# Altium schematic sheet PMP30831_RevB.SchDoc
size 431 x 279 mm; Date: Not shown in title block; ApprovedBy: Not shown in title block; CheckedBy: Not shown in title block; Author: Not shown in title block; CompanyName: Not shown in title block; Engineer: Not shown in title block; Organization: Not shown in title block; Address1: Not shown in title block; Address2: Not shown in title block; Address3: Not shown in title block; Address4: Not shown in title block; DocumentNumber: 2; Revision: Use project parameter SCH_Rev; SheetNumber: 2; SheetTotal: 3; PageSetup: Record=PageOptions¦CenterHorizontal=True¦CenterVertical=True¦PrintScale=1.00¦XCorrection=1.00¦YCorrection=1.00¦PrintKind=0¦BorderSize=5000000¦LeftOffset=0¦BottomOffset=0¦Orientation=2¦PaperLength=1000¦PaperWidth=1000¦Scale=100¦PaperSource=15¦PrintQuality=600¦MediaType=1¦DitherType=10¦PaperKind=Letter¦PrintScaleMode=1
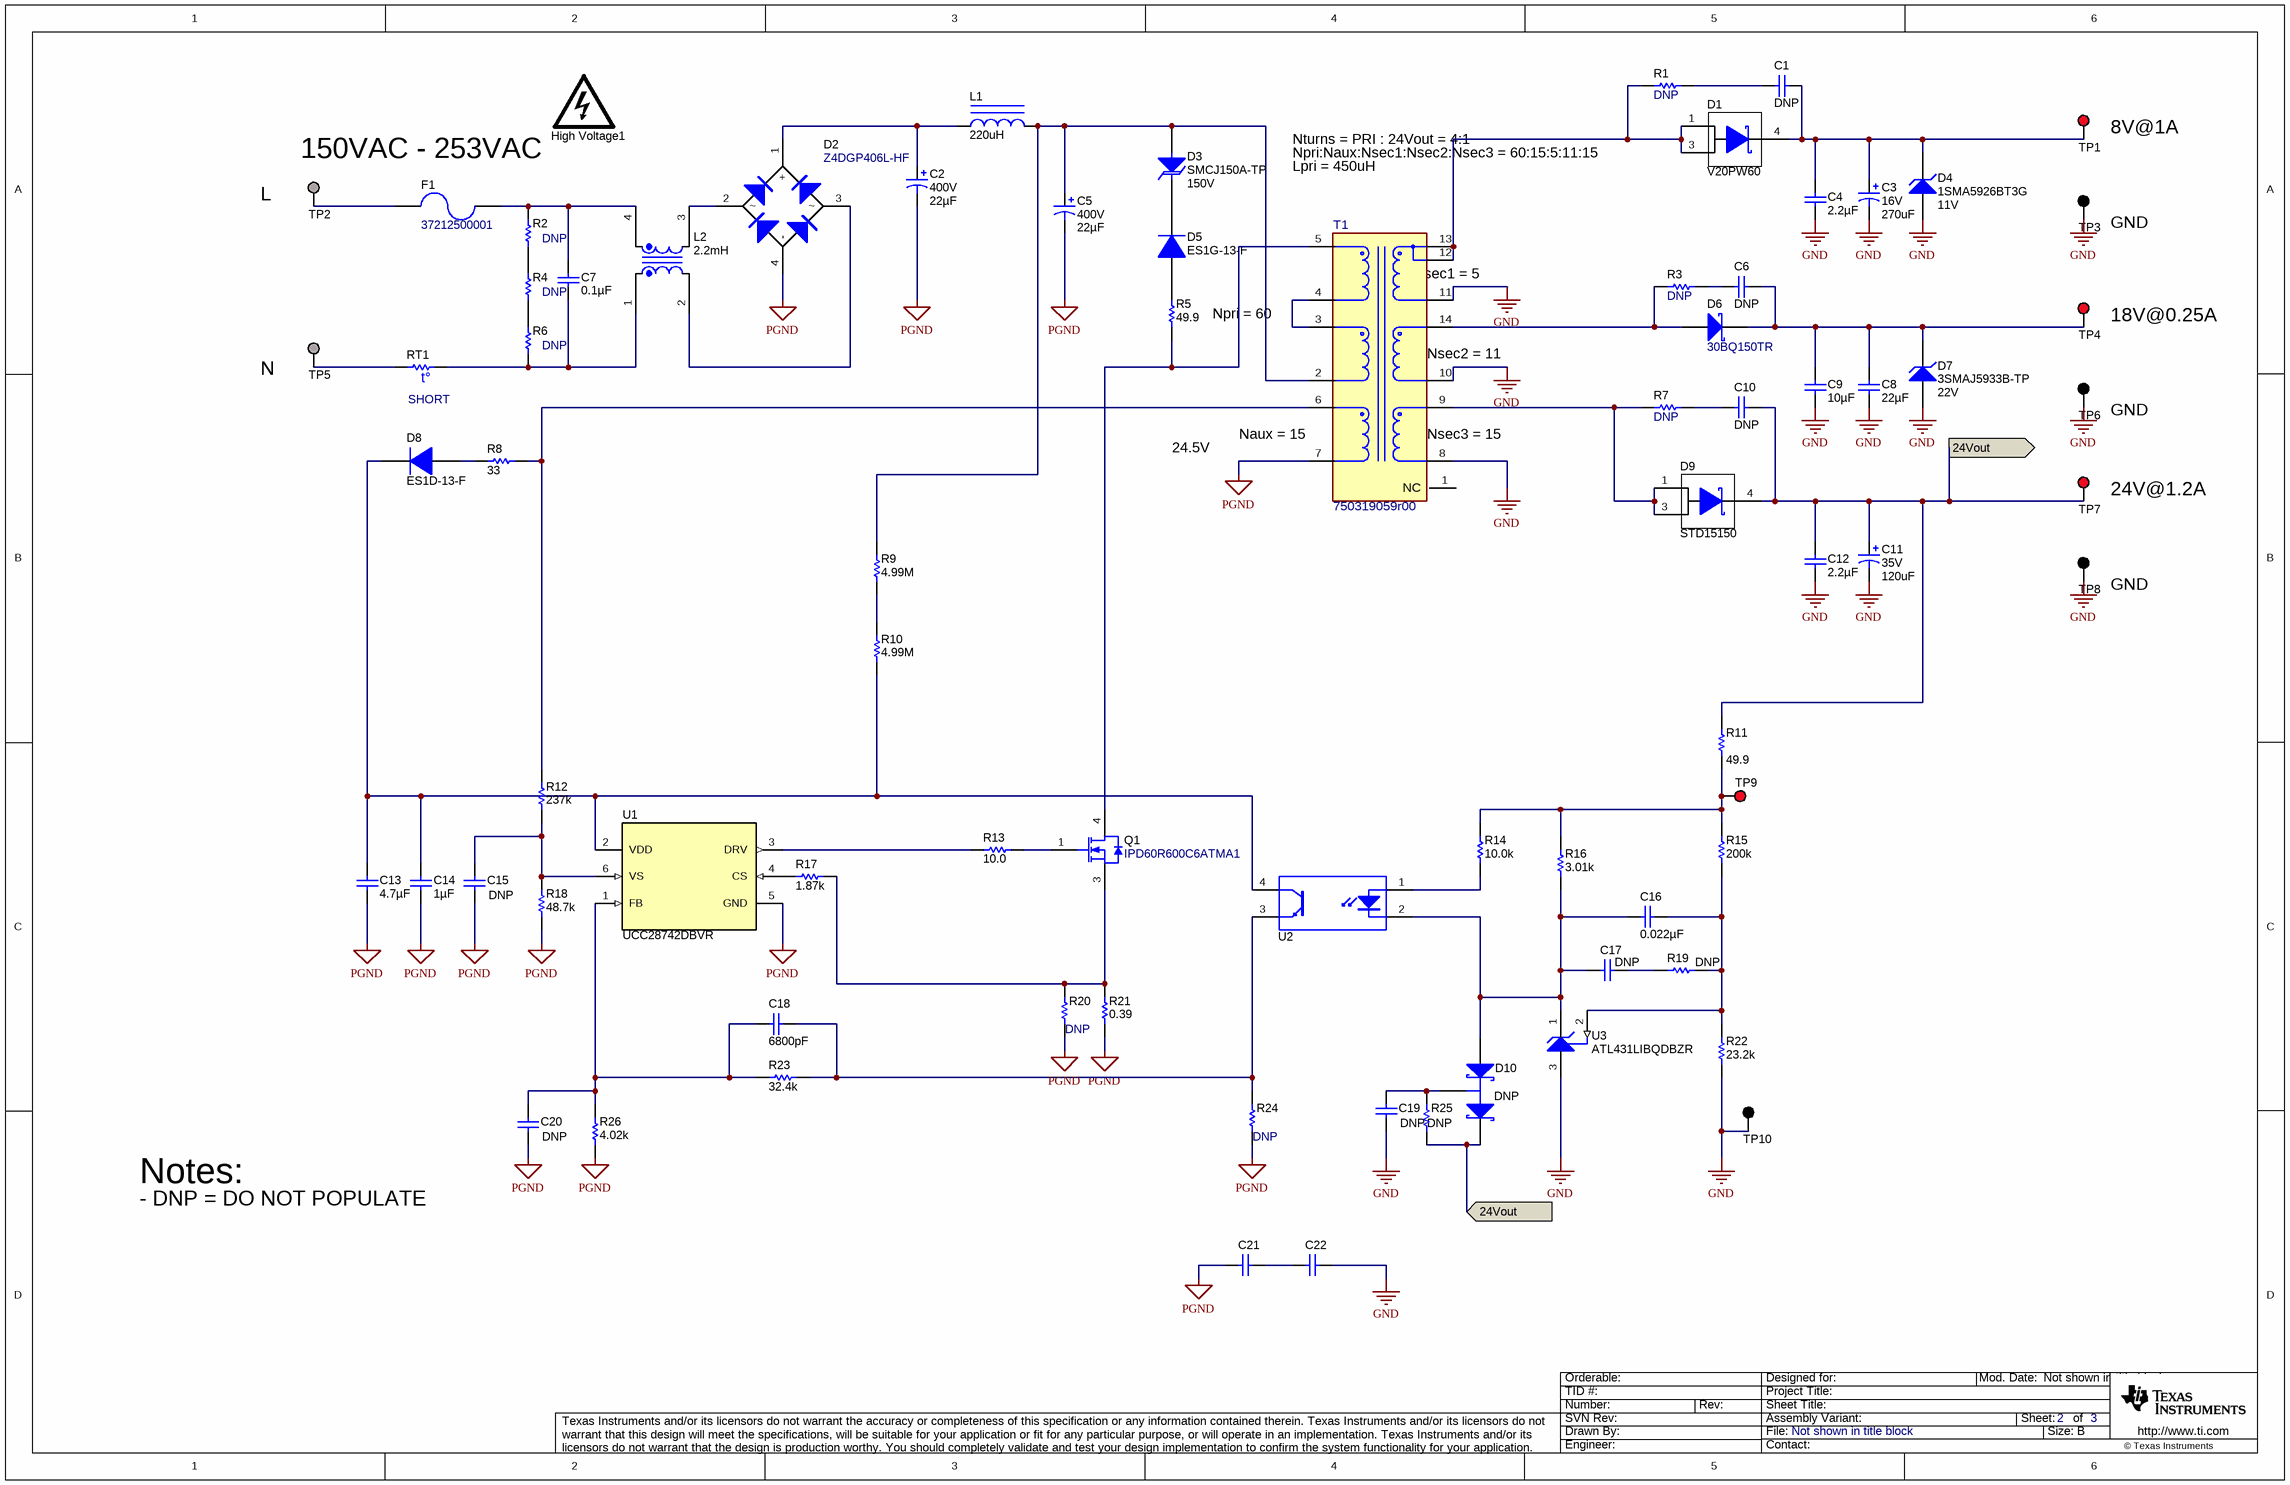
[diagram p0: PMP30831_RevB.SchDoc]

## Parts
C1  DNP  [0805_HV]
C2  VDC_V: 400V  ValueDisplayed: 22µF  [UCS_1250x2000]  (hidden comment: UCS2G220MHD)
C3  VDC_V: 16V  ValueDisplayed: 270uF  [SVPF_E7]  (hidden comment: 16SVPF270M)
C4  ValueDisplayed: 2.2µF  [1206]  (hidden comment: C1206C225K4RACTU)
C5  VDC_V: 400V  ValueDisplayed: 22µF  [UCS_1250x2000]  (hidden comment: UCS2G220MHD)
C6  DNP  [0805_HV]
C7  ValueDisplayed: 0.1µF  [WCAP-FTX2_1300x700x1300]  (hidden comment: 890324023023)
C8  ValueDisplayed: 22µF  [1210_270]  (hidden comment: GRM32ER61E226KE15L)
C9  ValueDisplayed: 10µF  [1210_220]  (hidden comment: GRM32DR71E106KA12L)
C10  DNP  [0805_HV]
C11  VDC_V: 35V  ValueDisplayed: 120uF  [CAPSMT_62_F12]  (hidden comment: 35SVPF120M)
C12  ValueDisplayed: 2.2µF  [1206_180]  (hidden comment: GRM31CR71H225KA88L)
C13  ValueDisplayed: 4.7µF  [1206_180]  (hidden comment: GRM31CR71H475KA12L)
C14  ValueDisplayed: 1µF  [0805_HV]  (hidden comment: C0805C105K5RACTU)
C15  value DNP  [0603]  (hidden comment: Used in BOM report)
C16  ValueDisplayed: 0.022µF  [0603]  (hidden comment: GRM188R71H223KA01D)
C17  value DNP  [0805]  (hidden comment: Used in BOM report)
C18  ValueDisplayed: 6800pF  [0603]  (hidden comment: GRM188R71H682KA01D)
C19  value DNP  [0805]  (hidden comment: Used in BOM report)
C20  value DNP  [0603]  (hidden comment: Used in BOM report)
C21  DE2E3KY152MN3AM02F  [KY_700x500x1000]  (value not drawn)
C22  DE2E3KY152MN3AM02F  [KY_700x500x1000]  (value not drawn)
D1  V20PW60  [DPAK]
D2  Z4DGP406L-HF  [Z4-D]
D3  SMCJ150A-TP  value 150V  [SMC]
D4  1SMA5926BT3G  value 11V  [SMA]
D5  ES1G-13-F  [SMA]
D6  30BQ150TR  [SMC_295]
D7  3SMAJ5933B-TP  value 22V  [SMA]
D8  ES1D-13-F  [SMA]
D9  STD15150  [DPAK]
D10  DNP  [SOT-23]
F1  37212500001  [FUSE_372]
High_Voltage1  DANGER HIGH VOLTAGE  [IEC_HighVoltage_Medium]  (value not drawn)  (no BOM)
L1  ValueDisplayed: 220uH  [DO3340P]  (hidden comment: DO3340P-224MLB)
L2  value 2.2mH  [WE-CMB_Type_S]  (hidden comment: 744822222)
Q1  IPD60R600C6ATMA1  [DPAK]
R1  DNP  [1206]
R2  value DNP  [1206]  (hidden comment: Used in BOM report)
R3  DNP  [1206]
R4  value DNP  [1206]  (hidden comment: Used in BOM report)
R5  ValueDisplayed: 49.9  [2512]  (hidden comment: CRCW251249R9FKEG)
R6  value DNP  [1206]  (hidden comment: Used in BOM report)
R7  DNP  [1206]
R8  ValueDisplayed: 33  [0805_HV]  (hidden comment: CRCW080533R0JNEA)
R9  ValueDisplayed: 4.99M  [0805_HV]  (hidden comment: CRCW08054M99FKEA)
R10  ValueDisplayed: 4.99M  [0805_HV]  (hidden comment: CRCW08054M99FKEA)
R11  ValueDisplayed: 49.9  [0603]  (hidden comment: CRCW060349R9FKEA)
R12  ValueDisplayed: 237k  [0603]  (hidden comment: CRCW0603237KFKEA)
R13  ValueDisplayed: 10.0  [0805_HV]  (hidden comment: CRCW080510R0FKEA)
R14  ValueDisplayed: 10.0k  [0603]  (hidden comment: CRCW060310K0FKEA)
R15  ValueDisplayed: 200k  [0603]  (hidden comment: CRCW0603200KFKEA)
R16  ValueDisplayed: 3.01k  [0603]  (hidden comment: CRCW06033K01FKEA)
R17  ValueDisplayed: 1.87k  [0603]  (hidden comment: CRCW06031K87FKEA)
R18  ValueDisplayed: 48.7k  [0603]  (hidden comment: CRCW060348K7FKEA)
R19  value DNP  [0603]  (hidden comment: Used in BOM report)
R20  DNP  [0805_HV]
R21  ValueDisplayed: 0.39  [0805_HV]  (hidden comment: ERJ-6RQFR39V)
R22  ValueDisplayed: 23.2k  [0603]  (hidden comment: CRCW060323K2FKEA)
R23  ValueDisplayed: 32.4k  [0603]  (hidden comment: CRCW060332K4FKEA)
R24  DNP  [0603_HV]
R25  value DNP  [0805]  (hidden comment: Used in BOM report)
R26  ValueDisplayed: 4.02k  [0603]  (hidden comment: CRCW06034K02FKEA)
RT1  SHORT  [TDK_B572]
T1  750319059r00  [FP-750319059r00_PTH_XFRMR_32MM25_27MM05-MFG]
TP1  5000  [Keystone5000]  (value not drawn)
TP2  Suggest using a net name here  [Keystone1503-2]  (value not drawn)
TP3  5001  [Keystone5001]  (value not drawn)
TP4  5000  [Keystone5000]  (value not drawn)
TP5  Suggest using a net name here  [Keystone1503-2]  (value not drawn)
TP6  5001  [Keystone5001]  (value not drawn)
TP7  5000  [Keystone5000]  (value not drawn)
TP8  5001  [Keystone5001]  (value not drawn)
TP9  5000  [Keystone5000]  (value not drawn)
TP10  5001  [Keystone5001]  (value not drawn)
U1  UCC28742DBVR  [DBV0006A_N]
U2  FOD817A  [DIP-4]  (value not drawn)
U3  ATL431LIBQDBZR  [DBZ0003A_N]

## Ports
24Vout (in), 24Vout (out)

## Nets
GND: C3.2(-) C4.2 C8.2 C9.2 C11.2(-) C12.2 C19.2 C22.1 D4.2(A) D7.2(A) R22.1 T1.8 T1.10 T1.11 TP3.1 TP6.1 TP8.1 TP10.1 U3.3(ANODE)
PGND: C2.2(-) C5.2(-) C13.2 C14.2 C15.2 C20.2 C21.2 D2.4(-) R18.1 R20.1 R21.1 R24.1 R26.1 T1.7 U1.5(GND)
24Vout: C10.2 C11.1(+) C12.1 D9.4(K) D10.2(K) R11.2 R25.1 TP7.1 ; port 24Vout
NetC1_1: C1.1 R1.1
NetC1_2: C1.2 C3.1(+) C4.1 D1.4(K) D4.1(K) TP1.1
NetC2_1: C2.1(+) D2.1(+) L1.1
NetC5_1: C5.1(+) D3.2(A) L1.2 R9.2 T1.2
NetC6_1: C6.1 R3.1
NetC6_2: C6.2 C8.1 C9.1 D6.1(K) D7.1(K) TP4.1
NetC7_1: C7.1 F1.1 L2.4 R2.2
NetC7_2: C7.2 L2.1 R6.1 RT1.2
NetC10_1: C10.1 R7.1
NetC13_1: C13.1 C14.1 D8.1(K) R10.1 U1.2(VDD) U2.4(C)
NetC15_1: C15.1 R12.1 R18.2 U1.6(VS)
NetC16_1: C16.1 R15.1 R19.1 R22.2 U3.2(REF)
NetC16_2: C16.2 C17.1 D10.1(A) R16.1 U2.2(K) U3.1(CATHODE)
NetC17_2: C17.2 R19.2
NetC18_1: C18.1 R23.2 R24.2 U2.3(E)
NetC18_2: C18.2 C20.1 R23.1 R26.2 U1.1(FB)
NetC19_1: C19.1 D10.3(C) R25.2
NetC21_1: C21.1 C22.2
NetD1_1: D1.1(A) D1.3(A) R1.2 T1.12 T1.13
NetD2_2: D2.2 L2.3
NetD2_3: D2.3 L2.2
NetD3_1: D3.1(K) D5.1(K)
NetD5_2: D5.2(A) R5.2
NetD6_2: D6.2(A) R3.2 T1.14
NetD8_2: D8.2(A) R8.1
NetD9_1: D9.1(A) D9.3(A) R7.2 T1.9
NetF1_2: F1.2 TP2.1
NetQ1_1: Q1.1(G) R13.2
NetQ1_3: Q1.3(S) R17.2 R20.2 R21.2
NetQ1_4: Q1.4(D) R5.1 T1.5
NetR2_1: R2.1 R4.2
NetR4_1: R4.1 R6.2
NetR8_2: R8.2 R12.2 T1.6
NetR9_1: R9.1 R10.2
NetR11_1: R11.1 R14.2 R15.2 R16.2 TP9.1
NetR13_1: R13.1 U1.3(DRV)
NetR14_1: R14.1 U2.1(A)
NetR17_1: R17.1 U1.4(CS)
NetRT1_1: RT1.1 TP5.1
NetT1_3: T1.3 T1.4

Not connected (* = marked no-connect by the designer): T1 1(NC)

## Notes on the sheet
- 150VAC - 253VAC
- Lpri = 450uH
- Npri:Naux:Nsec1:Nsec2:Nsec3 = 60:15:5:11:15
- Nturns = PRI : 24Vout = 4:1
- (near TP1) 8V@1A
- (near TP2) L
- (near TP3) GND
- (near T1) Nsec1 = 5
- Npri = 60
- (near T1) Nsec2 = 11
- (near TP4) 18V@0.25A
- (near TP5) N
- (near T1) Naux = 15
- (near T1) Nsec3 = 15
- (near TP6) GND
- 24.5V
- (near TP7) 24V@1.2A
- (near TP8) GND
- Notes:
- - DNP = DO NOT POPULATE

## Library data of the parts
C1 C6 C10 = Capacitor: CAP, CERM, xxxF, xxV, [TempCo], xx%, [PackageReference]; Manufacturer: Used in BOM report; Polarized: N; U/M: EA
C2 C5 = CMP-0081925-1: CAP, AL, 22 µF, 400 V, +/- 20%, TH; Manufacturer: Nichicon; TaMin_C: -40°C; Polarized: Y; SizeAreaWB_mm2: 210.25; U/M: EA; Value: 22uF; TaMax_C: 105°C; SizeZ_mm: 21.5; SizeX_mm: 12.5; Cap_Case: 12.5x20mm; SizeArea_mm2: 156.25; CompType: Capacitor; AEC Qualified: N; IRMS_A: 760mA; AEC Category: Q200
C3 = CMP-0012093-3: CAP, Aluminum Polymer, 270 uF, 16 V, +/- 20%, 0.022 ohm, 8.0x7.0mm SMD; Manufacturer: Panasonic; TaMin_C: -55°C; ESR_ohm: 0.022; Polarized: Y; Value: 270uF; TaMax_C: 105°C; CompType: Capacitor; Cap_F: 270µF; IRMS_A: 3.3A; AEC Category: Q200
C4 = C1206C225K4RACTU: CAP, CERM, 2.2 µF, 16 V,+/- 10%, X7R, 1206; Manufacturer: Kemet; Polarized: N; CompType: Capacitor; Value: 2.2uF; U/M: EA; Cap_F: 0.0000022; Tolerance_%: 10; ESR_ohm: 0.009; Value1: 0.009 ohm; VDC_V: 16; Value2: 16V; IRMS_A: 4.46; TaMin_C: -55; TaMax_C: 125; SizeArea_mm2: 5.12; SizeAreaWB_mm2: 10.92; SizeX_mm: 3.2; SizeY_mm: 1.6; SizeZ_mm: 1.35; AEC Category: Q200; Green_Lifecycle: Not Set; Green_REACh: Incomplete
C7 = CMP-0081647-2: CAP, Film, 0.1 µF,  V,+/- 10%, TH; Manufacturer: Wurth Elektronik; SizeArea_mm2: 91; SizeZ_mm: 13.5; Cap_Case: 13x7x13mm; SizeY_mm: 7; Value: 0.1uF; SizeX_mm: 13; TaMin_C: -40°C; AEC Category: Q200; AEC Qualified: N; Cap_F: 100nF; SizeAreaWB_mm2: 135; TaMax_C: 105°C
C8 = GRM32ER61E226KE15L: CAP, CERM, 22 µF, 25 V,+/- 10%, X5R, 1210; Manufacturer: MuRata; Polarized: N; CompType: Capacitor; Value: 22uF; U/M: EA; Cap_F: 0.000022; Tolerance_%: 10; ESR_ohm: 0.002; Value1: 0.002 ohm; VDC_V: 25; Value2: 25V; IRMS_A: 3.67; TaMin_C: -55; TaMax_C: 85; Cap_Case: 1210; SizeArea_mm2: 8; SizeAreaWB_mm2: 14.7; SizeX_mm: 3.2; SizeY_mm: 2.5; SizeZ_mm: 2.7; AEC Category: Q200; Green_Lifecycle: Active; Green_REACh: Passed
C9 = GRM32DR71E106KA12L: CAP, CERM, 10 µF, 25 V,+/- 10%, X7R, 1210; Manufacturer: MuRata; Polarized: N; CompType: Capacitor; Value: 10uF; U/M: EA; Cap_F: 0.00001; Tolerance_%: 10; VDC_V: 25; Value2: 25V; TaMin_C: -55; TaMax_C: 125; Cap_Case: 1210; SizeArea_mm2: 8; SizeAreaWB_mm2: 14.7; SizeX_mm: 3.2; SizeY_mm: 2.5; SizeZ_mm: 2.2; AEC Category: Q200
C11 = CMP-0012133-1: CAP, Aluminum Polymer, 120 uF, 35 V, +/- 20%, 0.018 ohm, F12, SMD, 2-Leads, Body 10.5x10.5mm, Height 12.7mm SMD; Manufacturer: Panasonic; TaMin_C: -55°C; ESR_ohm: 0.018; Polarized: Y; SizeAreaWB_mm2: 151.29; U/M: EA; Value: 120uF; TaMax_C: 105°C; SizeZ_mm: 12.6; SizeX_mm: 10.3; SizeArea_mm2: 106.09; CompType: Capacitor; AEC Qualified: N; Cap_F: 120µF; IRMS_A: 4.4A; AEC Category: Q200
C12 = GRM31CR71H225KA88L: CAP, CERM, 2.2 µF, 50 V,+/- 10%, X7R, 1206; Manufacturer: MuRata; Polarized: N; CompType: Capacitor; Value: 2.2uF; U/M: EA; Cap_F: 0.0000022; Tolerance_%: 10; VDC_V: 50; Value2: 50V; TaMin_C: -55; TaMax_C: 125; Cap_Case: 1206; SizeArea_mm2: 5.12; SizeAreaWB_mm2: 10.92; SizeX_mm: 3.2; SizeY_mm: 1.6; SizeZ_mm: 1.8; AEC Category: Q200; Green_Lifecycle: Active; Green_REACh: Passed
C13 = GRM31CR71H475KA12L: CAP, CERM, 4.7 µF, 50 V,+/- 10%, X7R, 1206; Manufacturer: MuRata; Polarized: N; CompType: Capacitor; Value: 4.7uF; U/M: EA; Cap_F: 0.0000047; Tolerance_%: 10; VDC_V: 50; Value2: 50V; TaMin_C: -55; TaMax_C: 125; Cap_Case: 1206; SizeArea_mm2: 5.12; SizeAreaWB_mm2: 10.92; SizeX_mm: 3.2; SizeY_mm: 1.6; SizeZ_mm: 1.8; AEC Category: Q200; Green_Lifecycle: Active; Green_REACh: Passed
C14 = C0805C105K5RACTU: CAP, CERM, 1 µF, 50 V,+/- 10%, X7R, 0805; Manufacturer: Kemet; Polarized: N; CompType: Capacitor; Value: 1uF; U/M: EA; Cap_F: 0.000001; Tolerance_%: 10; VDC_V: 50; Value2: 50V; TaMin_C: -55; TaMax_C: 125; Cap_Case: 0805; SizeArea_mm2: 2.5; SizeAreaWB_mm2: 6.75; SizeX_mm: 2; SizeY_mm: 1.25; SizeZ_mm: 1.45; AEC Category: Q200; Green_Lifecycle: Not Set; Green_REACh: Incomplete
C15 C17 C19 C20 = Capacitor: CAP, CERM, xxxF, xxV, [TempCo], xx%, [PackageReference]; Polarized: N; U/M: EA
C16 = GRM188R71H223KA01D: CAP, CERM, 0.022 µF, 50 V,+/- 10%, X7R, 0603; Manufacturer: MuRata; Polarized: N; CompType: Capacitor; Value: 0.022uF; U/M: EA; Cap_F: 0.000000022; Tolerance_%: 10; VDC_V: 50; Value2: 50V; TaMin_C: -55; TaMax_C: 125; SizeArea_mm2: 1.28; SizeAreaWB_mm2: 4.68; SizeX_mm: 1.6; SizeY_mm: 0.8; SizeZ_mm: 1; AEC Category: Q200; Green_Lifecycle: Active; Green_REACh: Passed
C18 = GRM188R71H682KA01D: CAP, CERM, 6800 pF, 50 V,+/- 10%, X7R, 0603; Manufacturer: MuRata; Polarized: N; CompType: Capacitor; Value: 6800pF; U/M: EA; Cap_F: 0.0000000068; Tolerance_%: 10; VDC_V: 50; Value2: 50V; TaMin_C: -55; TaMax_C: 125; SizeArea_mm2: 1.28; SizeAreaWB_mm2: 4.68; SizeX_mm: 1.6; SizeY_mm: 0.8; SizeZ_mm: 1; AEC Category: Q200; Green_Lifecycle: Active; Green_REACh: Passed
C21 C22 = DE2E3KY152MN3AM02F: CAP, CERM, 1500 pF, X1 250 VAC/Y2 300 VAC, +/- 20%, E, TH, 2- Leads, Body 7x5mm, Pin Spacing 7.5mm; Manufacturer: MuRata; Polarized: N; CompType: Capacitor; Value: 1500pF; U/M: EA; Cap_F: 0.0000000015; Tolerance_%: 20; TaMin_C: -25; TaMax_C: 85; Cap_Case: 7x5x10mm; SizeArea_mm2: 37.5; SizeAreaWB_mm2: 66.5; SizeX_mm: 7.5; SizeY_mm: 5; SizeZ_mm: 10; AEC Category: Q200; AC_Safety: X1Y2; VAC_X: 250; VAC_Y: 300
D1 = DIODE_SCHOTTKY_A13C4: Diode, Schottky,60V,20A, [PackageReference]; Manufacturer: Vishay; U/M: EA
D2 = CMP-0029244-3: Diode, P-N-Bridge, 600 V, 4 A, Z4-D; Manufacturer: Comchip Technology; Value1: 4A; SizeZ_mm: 1.55; Value: 600V; SizeArea_mm2: 85.05; SizeY_mm: 8.1; SizeAreaWB_mm2: 126.25; Value2: 0.95V; Green_REACh: Incomplete; TJmax_C: 175°C; Green_Lifecycle: Not Set; Vf_V: 950mV; AEC Qualified: N; AEC Category: Q101; SizeX_mm: 10.5
D3 = SMCJ150A-TP: Diode, TVS, Uni, 150 V, 243 Vc, SMC; Manufacturer: Micro Commercial Components; U/M: EA; Vr_V: 150; Value1: W; SizeAreaWB_mm2: 83.2686; SizeArea_mm2: 50.5686; SizeX_mm: 8.13; SizeY_mm: 6.22; SizeZ_mm: 2.6; AEC Category: Q101; AEC Qualified: N
D4 = 1SMA5926BT3G: Diode, Zener, 11 V, 1.5 W, SMA; Manufacturer: ON Semiconductor; SymbolCreator: a0412235; U/M: EA; Power_W: 1.5; Vz_V: 11; Value1: 1.5W; RJA_CperW: 250; SizeAreaWB_mm2: 37.3428; SizeArea_mm2: 16.3228; SizeX_mm: 5.59; SizeY_mm: 2.92; SizeZ_mm: 2.87; AEC Category: Q101
D5 = ES1G-13-F: Diode, Superfast Rectifier, 400 V, 1 A, SMA; Manufacturer: Diodes Inc.; U/M: EA; Vf_V: 1.25; Value: 400V; Value1: 1A; Value2: 1.25V; Io_A: 1; Vr_V: 400; TJmax_C: 150; RJC_CperW: 25; SizeAreaWB_mm2: 37.3428; SizeArea_mm2: 16.3228; SizeX_mm: 5.59; SizeY_mm: 2.92; SizeZ_mm: 2.87; AEC Category: Q101; Green_Lifecycle: Active; Green_REACh: Passed
D6 = CMP-0083842-2: Diode, Schottky, 150 V, 3 A, SMC; Manufacturer: SMC Diode Solutions; Io_A: 3A; SizeZ_mm: 2.95; Vr_V: 150V; Value: 150V; Value2: 0.86V; AEC Category: Q101; SizeX_mm: 8; AEC Qualified: N; TJmax_C: 175°C; Vf_V: 860mV; SizeAreaWB_mm2: 79.05; SizeArea_mm2: 47.24; SizeY_mm: 5.905
D7 = 3SMAJ5933B-TP: Diode, Zener, 22 V, 3 W, SMA; Manufacturer: Micro Commercial Components; SymbolCreator: a0412235; U/M: EA; Power_W: 3; Vz_V: 22; Value1: 3W; RJA_CperW: 226; SizeAreaWB_mm2: 37.3428; SizeArea_mm2: 16.3228; SizeX_mm: 5.59; SizeY_mm: 2.92; SizeZ_mm: 2.87; AEC Category: Q101
D8 = ES1D-13-F: Diode, Ultrafast, 200 V, 1 A, SMA; Manufacturer: Diodes Inc.; U/M: EA; Vf_V: 0.92; Value: 200V; Value1: 1A; Value2: 0.92V; Io_A: 1; Vr_V: 200; TJmax_C: 150; RJC_CperW: 25; SizeAreaWB_mm2: 37.3428; SizeArea_mm2: 16.3228; SizeX_mm: 5.59; SizeY_mm: 2.92; SizeZ_mm: 2.87; AEC Category: Q101; Green_Lifecycle: Active; Green_REACh: Passed
D9 = DIODE_SCHOTTKY_A13C4: Diode, Schottky,150V,15A, [PackageReference]; Manufacturer: SMC Diode Solutions; U/M: EA
D10 = BAT54S-7-F: Diode, Schottky, 30 V, 0.2 A, SOT-23; Manufacturer: Diodes Inc.; U/M: EA; Vf_V: 0.65; Value1: 0.2A; Value2: 0.65V; Io_A: 0.2; Vr_V: 30; TJmax_C: 125; SizeAreaWB_mm2: 14; SizeArea_mm2: 7.5; SizeX_mm: 2.5; SizeY_mm: 3; SizeZ_mm: 1.1; AEC Category: Q101
F1 = CMP-0003556-2: Fuse, 2.5 A, 250VAC/VDC, TH; Manufacturer: Littelfuse; Irating_A: 2.5A; VAC_V: 250V
High_Voltage1 = IEC_HighVoltage: IEC 61010-1 High Voltage Warning; SymbolCreator: a0412235
L1 = CMP-0061709-2: Inductor, Drum Core, Ferrite, 220 uH, 0.7 A, 0.44 ohm, SMD; Manufacturer: Coilcraft; Isat: 1.6A @ 10% inductance drop; Irms: 0.7A @ 20C rise; Green_Lifecycle: Not Set; SizeAreaWB_mm2: 170.43; DCR_ohm: 0.44; Green_REACh: Incomplete; Value: 220uH; Imax_A: 700mA; SizeZ_mm: 11.43; SizeX_mm: 12.95; SizeY_mm: 9.4; Value2: 0.7A; SizeArea_mm2: 121.73; Ind_H: 220µH; AEC Category: Q200
L2 = CMP-0013143-1: Coupled inductor, 2.2 mH,  A, 0.07 ohm, TH; Manufacturer: Wurth Elektronik; DCR_ohm: 0.07
Q1 = CMP-0001165-1: MOSFET, N-CH, 600 V, 7.3 A, AEC-Q101, DPAK; Alternate Manufacturer: None; Manufacturer: Infineon Technologies; SizeZ_mm: 2.29; ChType: N; Value2: 20.5 nC; VdsMax_V: 600V; SizeX_mm: 9.91; SizeY_mm: 6.54; Vgs_V: 20V; QgTyp_nC: 20.5; AEC Qualified: Y; Value: 600V; SizeArea_mm2: 64.8114; AEC Category: Q101; IdsMax_A: 7.3A; SizeAreaWB_mm2: 101.7114; U/M: EA
R1 R3 R7 R20 R24 = Resistor: RES, xxx ohm, x%, xW, [PackageReference]; Manufacturer: Used in BOM report; U/M: EA
R2 R4 R6 R19 R25 = Resistor: RES, xxx ohm, x%, xW, [PackageReference]; U/M: EA
R5 = CRCW251249R9FKEG: RES, 49.9, 1%, 1 W, AEC-Q200 Grade 0, 2512; Manufacturer: Vishay-Dale; CompType: Resistor; Value: 49.9; Value_Code: 49R9; Tolerance_%: 1; Value2: 1W; VDC_V: 500; TempCo: 100 ppm/C; SizeArea_mm2: 20.16; SizeX_mm: 6.3; SizeY_mm: 3.2; SizeZ_mm: 0.71; EIA_Code: E96; U/M: EA; AEC Category: Q200; AEC Qualified: Y; AEC Grade: 0; Green_Lifecycle: Active; Green_REACh: Passed
R8 = CRCW080533R0JNEA: RES, 33, 5%, 0.125 W, 0805; Manufacturer: Vishay-Dale; CompType: Resistor; Value: 33; Value_Code: 33R0; Tolerance_%: 5; Power_W: 0.125; Value2: 0.125W; VDC_V: 150; TempCo: 200 ppm/C; SizeArea_mm2: 2.5; SizeX_mm: 2; SizeY_mm: 1.25; SizeZ_mm: 1.45; EIA_Code: E24; U/M: EA; AEC Category: Q200; Green_Lifecycle: Active; Green_REACh: Passed
R9 R10 = CRCW08054M99FKEA: RES, 4.99 M, 1%, 0.125 W, 0805; Manufacturer: Vishay-Dale; CompType: Resistor; Value: 4.99Meg; Res_ohm: 4990000; Value_Code: 4M99; Tolerance_%: 1; Power_W: 0.125; Value2: 0.125W; VDC_V: 150; TempCo: 100 ppm/C; SizeArea_mm2: 2.5; SizeX_mm: 2; SizeY_mm: 1.25; SizeZ_mm: 1.45; EIA_Code: E96; U/M: EA; AEC Category: Q200
R11 = CRCW060349R9FKEA: RES, 49.9, 1%, 0.1 W, 0603; Manufacturer: Vishay-Dale; CompType: Resistor; Value: 49.9; Value_Code: 49R9; Tolerance_%: 1; Power_W: 0.1; Value2: 0.1W; VDC_V: 75; TempCo: 100 ppm/C; SizeArea_mm2: 1.28; SizeX_mm: 1.6; SizeY_mm: 0.8; EIA_Code: E96; U/M: EA; AEC Category: Q200
R12 = CRCW0603237KFKEA: RES, 237 k, 1%, 0.1 W, 0603; Manufacturer: Vishay-Dale; CompType: Resistor; Value: 237k; Res_ohm: 237000; Tolerance_%: 1; Power_W: 0.1; Value2: 0.1W; VDC_V: 75; TempCo: 100 ppm/C; SizeArea_mm2: 1.28; SizeX_mm: 1.6; SizeY_mm: 0.8; EIA_Code: E96; U/M: EA; AEC Category: Q200; Green_Lifecycle: Active; Green_REACh: Passed
R13 = CRCW080510R0FKEA: RES, 10.0, 1%, 0.125 W, 0805; Manufacturer: Vishay-Dale; CompType: Resistor; Value: 10.0; Res_ohm: 10; Value_Code: 10R0; Tolerance_%: 1; Power_W: 0.125; Value2: 0.125W; VDC_V: 150; TempCo: 100 ppm/C; SizeArea_mm2: 2.5; SizeX_mm: 2; SizeY_mm: 1.25; SizeZ_mm: 1.45; EIA_Code: E96; U/M: EA; AEC Category: Q200; Green_Lifecycle: Active; Green_REACh: Passed
R14 = CRCW060310K0FKEA: RES, 10.0 k, 1%, 0.1 W, 0603; Manufacturer: Vishay-Dale; CompType: Resistor; Value: 10.0k; Res_ohm: 10000; Value_Code: 10k0; Tolerance_%: 1; Power_W: 0.1; Value2: 0.1W; VDC_V: 75; TempCo: 100 ppm/C; SizeArea_mm2: 1.28; SizeX_mm: 1.6; SizeY_mm: 0.8; EIA_Code: E96; U/M: EA; AEC Category: Q200; Green_Lifecycle: Active; Green_REACh: Passed
R15 = CRCW0603200KFKEA: RES, 200 k, 1%, 0.1 W, 0603; Manufacturer: Vishay-Dale; CompType: Resistor; Value: 200k; Res_ohm: 200000; Tolerance_%: 1; Power_W: 0.1; Value2: 0.1W; VDC_V: 75; TempCo: 100 ppm/C; SizeArea_mm2: 1.28; SizeX_mm: 1.6; SizeY_mm: 0.8; EIA_Code: E96; U/M: EA; AEC Category: Q200; Green_Lifecycle: Active; Green_REACh: Passed
R16 = CRCW06033K01FKEA: RES, 3.01 k, 1%, 0.1 W, 0603; Manufacturer: Vishay-Dale; CompType: Resistor; Value: 3.01k; Res_ohm: 3010; Value_Code: 3k01; Tolerance_%: 1; Power_W: 0.1; Value2: 0.1W; VDC_V: 75; TempCo: 100 ppm/C; SizeArea_mm2: 1.28; SizeX_mm: 1.6; SizeY_mm: 0.8; EIA_Code: E96; U/M: EA; AEC Category: Q200; Green_Lifecycle: Active; Green_REACh: Passed
R17 = CRCW06031K87FKEA: RES, 1.87 k, 1%, 0.1 W, 0603; Manufacturer: Vishay-Dale; CompType: Resistor; Value: 1.87k; Res_ohm: 1870; Value_Code: 1k87; Tolerance_%: 1; Power_W: 0.1; Value2: 0.1W; VDC_V: 75; TempCo: 100 ppm/C; SizeArea_mm2: 1.28; SizeX_mm: 1.6; SizeY_mm: 0.8; EIA_Code: E96; U/M: EA; AEC Category: Q200; Green_Lifecycle: Active; Green_REACh: Passed
R18 = CRCW060348K7FKEA: RES, 48.7 k, 1%, 0.1 W, 0603; Manufacturer: Vishay-Dale; CompType: Resistor; Value: 48.7k; Res_ohm: 48700; Value_Code: 48k7; Tolerance_%: 1; Power_W: 0.1; Value2: 0.1W; VDC_V: 75; TempCo: 100 ppm/C; SizeArea_mm2: 1.28; SizeX_mm: 1.6; SizeY_mm: 0.8; EIA_Code: E96; U/M: EA; AEC Category: Q200; Green_Lifecycle: Active; Green_REACh: Passed
R21 = ERJ-6RQFR39V: RES, 0.39, 1%, 0.125 W, 0805; Manufacturer: Panasonic; CompType: Resistor; Value: 0.39; Value_Code: R390; Tolerance_%: 1; Power_W: 0.125; Value2: 0.125W; TempCo: 250 ppm/C; SizeArea_mm2: 2.5; SizeX_mm: 2; SizeY_mm: 1.25; SizeZ_mm: 1.45; EIA_Code: E96; U/M: EA; AEC Category: Q200
R22 = CRCW060323K2FKEA: RES, 23.2 k, 1%, 0.1 W, 0603; Manufacturer: Vishay-Dale; CompType: Resistor; Value: 23.2k; Res_ohm: 23200; Value_Code: 23k2; Tolerance_%: 1; Power_W: 0.1; Value2: 0.1W; VDC_V: 75; TempCo: 100 ppm/C; SizeArea_mm2: 1.28; SizeX_mm: 1.6; SizeY_mm: 0.8; EIA_Code: E96; U/M: EA; AEC Category: Q200; Green_Lifecycle: Active; Green_REACh: Passed
R23 = CRCW060332K4FKEA: RES, 32.4 k, 1%, 0.1 W, 0603; Manufacturer: Vishay-Dale; CompType: Resistor; Value: 32.4k; Res_ohm: 32400; Value_Code: 32k4; Tolerance_%: 1; Power_W: 0.1; Value2: 0.1W; VDC_V: 75; TempCo: 100 ppm/C; SizeArea_mm2: 1.28; SizeX_mm: 1.6; SizeY_mm: 0.8; EIA_Code: E96; U/M: EA; AEC Category: Q200; Green_Lifecycle: Active; Green_REACh: Passed
R26 = CRCW06034K02FKEA: RES, 4.02 k, 1%, 0.1 W, 0603; Manufacturer: Vishay-Dale; CompType: Resistor; Value: 4.02k; Res_ohm: 4020; Value_Code: 4k02; Tolerance_%: 1; Power_W: 0.1; Value2: 0.1W; VDC_V: 75; TempCo: 100 ppm/C; SizeArea_mm2: 1.28; SizeX_mm: 1.6; SizeY_mm: 0.8; EIA_Code: E96; U/M: EA; AEC Category: Q200; Green_Lifecycle: Active; Green_REACh: Passed
RT1 = CMP-0002558-1: Thermistor NTC, 5 ohm, 20%, D14.5xT7mm; Manufacturer: TDK; TaMax_C: 150°C; TaMin_C: -40°C; Power_W: 3.8W; U/M: EA
T1 = CMP-0088857-1: TRANSFORMER; Manufacturer: Wurth Electronics; Ns1toNp: 4:1/4:1/5.45:1/12:1; Voltage_Isolation_Vrms: 3.8kV; AEC Qualified: No; SizeZ_mm: 22.86mm; Frequency_Fixed: 65kHz; Ind_H: 450µH; DCR_ohm: 0.5
TP1 TP4 TP7 = 5000: Test Point, Miniature, Red, TH; Manufacturer: Keystone; CompType: Test Point Loop; ContactFinish: Silver; Green_Lifecycle: Active; Green_REACh: Passed
TP2 TP5 = 1503-2: Terminal, Turret, TH, Double; Manufacturer: Keystone; CompType: Turret Terminal; U/M: EA
TP3 TP6 TP8 TP10 = 5001: Test Point, Miniature, Black, TH; Manufacturer: Keystone; CompType: Test Point Loop; ContactFinish: Silver; Green_Lifecycle: Active; Green_REACh: Passed
TP9 = 5000: Test Point, Miniature, Red, TH; Manufacturer: Keystone; CompType: Test Point Loop; ContactFinish: Silver
U1 = CMP-0078369-2: High-Efficiency Low-Cost Flyback Controller with Secondary-Side Regulation, DBV0006A (SOT-23-6); Manufacturer: Texas Instruments; SizeZ_mm: 1.45; SizeX_mm: 2.8; SizeY_mm: 2.9; AEC Category: Q200; AEC Qualified: N; SizeArea_mm2: 8.12; CompType: IC; SizeAreaWB_mm2: 14.82
U2 = FOD817A: Optocoupler, 5 kV, 80-160% CTR, TH; Manufacturer: Fairchild Semiconductor; CTR (Min): 80%; CTR (Max): 160%; Voltage_Isolation_Vrms: 5000V; SizeAreaWB_mm2: 71.064; SizeArea_mm2: 40.304; SizeX_mm: 8.8; SizeY_mm: 4.58; SizeZ_mm: 5
U3 = CMP-0084731-1: High Bandwidth Low-Iq Programmable Shunt Regulator, DBZ0003A (SOT-23-3); Manufacturer: Texas Instruments; CompType: IC; SizeX_mm: 2.5; AEC Category: Q200; SizeY_mm: 3; SizeArea_mm2: 7.5; AEC Qualified: N; SizeZ_mm: 1.12; SizeAreaWB_mm2: 14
